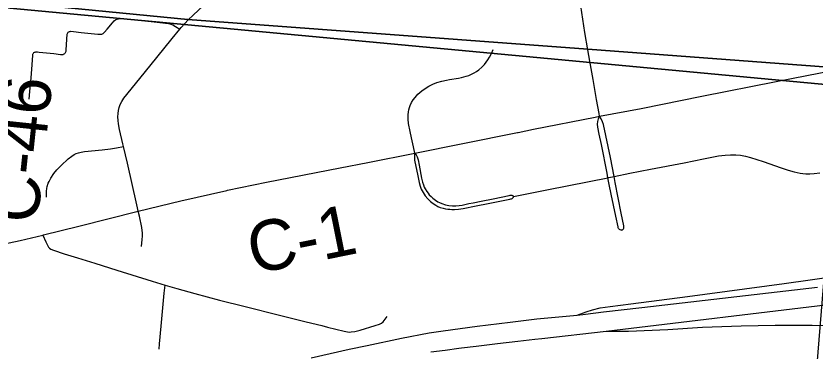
# Model space of a CAD drawing. Extents: x 0 to 34, y 0 to 22.
# Drawn here: x 22.884 to 23.785, y 14.548 to 14.925 of the extents above; entities that cross this region are included whole.
import ezdxf

# ---------------------------------------------------------------- set-up
doc = ezdxf.new("R2010")
doc.units = 0
for name, color, linetype in [('GM_X_City_Street', 7, 'Continuous'), ('GM_X_County_Road', 7, 'Continuous'), ('GM_X_County_Road_Text', 7, 'Continuous'), ('GM_X_Interstate_Route', 7, 'Continuous'), ('GM_X_Section', 7, 'Continuous'), ('GM_X_State_Route', 7, 'Continuous'), ('SH_Border', 7, 'Continuous')]:
    doc.layers.add(name, color=color, linetype=linetype)

msp = doc.modelspace()

# ---------------------------------------------------------------- linework, layer by layer
at = {"layer": 'GM_X_City_Street'}
for points in [[(23.54188, 14.81222), (23.54135, 14.8153), (23.53864, 14.83109), (23.53457, 14.85351), (23.53099, 14.87419), (23.52877, 14.88721), (23.52533, 14.90673), (23.52084, 14.93684), (23.51346, 14.98347), (23.51038, 15.00249), (23.50897, 15.01211), (23.50831, 15.01773), (23.50782, 15.02416), (23.5076, 15.03291), (23.50781, 15.0404), (23.50864, 15.05098), (23.51075, 15.06952), (23.51341, 15.09235), (23.51548, 15.11099)], [(22.94277, 14.90686), (22.94344, 14.90733), (22.94423, 14.90776), (22.94503, 14.90796), (22.946, 14.90799), (22.94886, 14.90772), (22.95749, 14.90677), (22.9761, 14.90474), (22.97875, 14.90463), (22.97967, 14.90467), (22.98075, 14.90496), (22.98211, 14.90571), (22.98372, 14.90698), (22.98666, 14.91035), (22.99264, 14.91759), (22.99465, 14.91978), (22.99649, 14.92115), (22.99801, 14.92186), (22.99963, 14.92225)], [(22.99963, 14.92225), (23.00162, 14.92232), (23.00777, 14.92191), (23.02562, 14.92018), (23.03981, 14.9187), (23.05593, 14.9168), (23.05873, 14.91623), (23.06081, 14.91529), (23.06376, 14.91342), (23.06876, 14.91026)], [(22.90429, 14.88402), (22.90496, 14.88431), (22.90562, 14.88456), (22.90636, 14.88474), (22.90717, 14.88481), (22.90826, 14.88478), (22.91011, 14.88462), (22.92679, 14.88281), (22.93419, 14.88199), (22.93623, 14.88187), (22.937, 14.88196), (22.93772, 14.88218), (22.93844, 14.88254), (22.93905, 14.88302), (22.93958, 14.88362), (22.93998, 14.88428), (22.94024, 14.88495), (22.94047, 14.88579), (22.94065, 14.88696), (22.94176, 14.9046), (22.94197, 14.90557), (22.94229, 14.90626), (22.94277, 14.90686)], [(22.89882, 14.8314), (22.89956, 14.84008), (22.90092, 14.85552), (22.90221, 14.87028), (22.90291, 14.88129), (22.90306, 14.88224), (22.90328, 14.88286), (22.9037, 14.8835), (22.90429, 14.88402)], [(23.33377, 14.77073), (23.33215, 14.77776), (23.32983, 14.78778), (23.32829, 14.79507), (23.32666, 14.80393), (23.32618, 14.8088), (23.32615, 14.81368), (23.3265, 14.81729), (23.32692, 14.81934), (23.32764, 14.82213), (23.32833, 14.82428), (23.32982, 14.82758), (23.33189, 14.83087), (23.33384, 14.83358), (23.33718, 14.83716), (23.3414, 14.84081), (23.34525, 14.84364), (23.34937, 14.84621), (23.3539, 14.84835), (23.35831, 14.85014), (23.36419, 14.85189), (23.36926, 14.85301), (23.37269, 14.85367), (23.38288, 14.85531), (23.38633, 14.85596), (23.38907, 14.85658), (23.39166, 14.85731), (23.39465, 14.85834), (23.39811, 14.85992), (23.40073, 14.86138), (23.40305, 14.86283), (23.40563, 14.86463), (23.409, 14.8675), (23.41209, 14.87069), (23.41419, 14.87333), (23.4161, 14.87599), (23.41798, 14.87893), (23.41998, 14.8829), (23.42194, 14.88756)], [(23.56703, 14.68388), (23.56634, 14.68388), (23.56514, 14.68417), (23.56445, 14.68457), (23.56391, 14.68509), (23.56342, 14.68577), (23.56306, 14.68656), (23.56271, 14.68765), (23.56033, 14.69951), (23.55488, 14.72437), (23.55272, 14.73532), (23.55135, 14.74301), (23.55044, 14.74815), (23.54403, 14.78039), (23.54157, 14.79192), (23.53997, 14.79981), (23.53975, 14.80343), (23.54003, 14.80631), (23.5408, 14.80929), (23.54188, 14.81222)], [(23.56703, 14.68388), (23.56762, 14.68411), (23.56859, 14.68494), (23.56896, 14.68554), (23.56919, 14.68618), (23.56942, 14.68692), (23.56946, 14.6877), (23.56938, 14.68871), (23.56639, 14.70293), (23.55954, 14.73769), (23.55835, 14.74442), (23.55423, 14.76578), (23.54635, 14.80287), (23.54522, 14.80601), (23.54378, 14.80934), (23.54188, 14.81222)], [(22.91835, 14.72097), (22.9185, 14.72794), (22.91871, 14.73067), (22.91916, 14.73323), (22.92036, 14.73666), (22.92133, 14.73887), (22.92335, 14.74265), (22.92669, 14.7477), (22.93, 14.75172), (22.93479, 14.75692), (22.94298, 14.76445), (22.94678, 14.76744), (22.94955, 14.76927), (22.95192, 14.77034), (22.95434, 14.77114), (22.95759, 14.77193), (22.96126, 14.77235), (22.98125, 14.77446), (22.99056, 14.77559), (22.99732, 14.77685), (23.00505, 14.7783)], [(23.33377, 14.77073), (23.3334, 14.76869), (23.33325, 14.76646), (23.33331, 14.76512), (23.33342, 14.76265), (23.33702, 14.74511), (23.33841, 14.73777), (23.33958, 14.73357), (23.34094, 14.7301), (23.34295, 14.72624), (23.34536, 14.72261), (23.34814, 14.71926), (23.35127, 14.71623), (23.35421, 14.71393), (23.35738, 14.71194), (23.35971, 14.71062), (23.3623, 14.70958), (23.36544, 14.70867), (23.3683, 14.70804), (23.37074, 14.70762), (23.37304, 14.70735), (23.37528, 14.7072), (23.37835, 14.7072), (23.38275, 14.70758), (23.3883, 14.70833), (23.40295, 14.71124), (23.41639, 14.71386), (23.4371, 14.71816), (23.44078, 14.71886), (23.44191, 14.71909), (23.44273, 14.71935), (23.44334, 14.71966), (23.44394, 14.72009), (23.44437, 14.7206), (23.44471, 14.72123), (23.44501, 14.72198)], [(23.33377, 14.77073), (23.33532, 14.76869), (23.33638, 14.76635), (23.33741, 14.76321), (23.33855, 14.75707), (23.34134, 14.74256), (23.34232, 14.73802), (23.34336, 14.73489), (23.34434, 14.73244), (23.34546, 14.73028), (23.34706, 14.72756), (23.34853, 14.7256), (23.34993, 14.72379), (23.35202, 14.72163), (23.35397, 14.71989), (23.35693, 14.71763), (23.35948, 14.7159), (23.36164, 14.71486), (23.36407, 14.71386), (23.3682, 14.71249), (23.37184, 14.71168), (23.37616, 14.71116), (23.37993, 14.71116), (23.3837, 14.71158), (23.38705, 14.71221), (23.39452, 14.71377), (23.39938, 14.71481), (23.40851, 14.71669), (23.42194, 14.7193), (23.43993, 14.72305), (23.44102, 14.7232), (23.44202, 14.72326), (23.44296, 14.72317), (23.44377, 14.72295), (23.44448, 14.72255), (23.44501, 14.72198)], [(23.44501, 14.72198), (23.48424, 14.72973), (23.55135, 14.74301), (23.55247, 14.74324), (23.55835, 14.74442), (23.57622, 14.74802), (23.59937, 14.75251), (23.63717, 14.7599), (23.65912, 14.76425), (23.67613, 14.76753), (23.6834, 14.76854), (23.68944, 14.76892), (23.69549, 14.76881), (23.70091, 14.76828), (23.70627, 14.76735), (23.71215, 14.76582), (23.72624, 14.76125), (23.74672, 14.75395), (23.75445, 14.75134), (23.76115, 14.74951), (23.76801, 14.74818), (23.77103, 14.7477), (23.77435, 14.74743), (23.77884, 14.74733), (23.78395, 14.74761), (23.79024, 14.74844)], [(23.02543, 14.66535), (23.0263, 14.67333), (23.02655, 14.67722), (23.02651, 14.6808), (23.02637, 14.6836), (23.02594, 14.68677), (23.02309, 14.69959), (23.0218, 14.70512)], [(22.91411, 14.6783), (22.91765, 14.67062), (22.91938, 14.66688), (22.92067, 14.6648), (22.92175, 14.66351), (22.92326, 14.6625), (22.92613, 14.66135), (22.93848, 14.65737), (22.95333, 14.65279), (22.97287, 14.6466), (22.99774, 14.6387), (23.03753, 14.62645), (23.05208, 14.62199), (23.06538, 14.61793), (23.08574, 14.6124), (23.11343, 14.60506), (23.14233, 14.59774), (23.1809, 14.58795), (23.19479, 14.58453), (23.21108, 14.58049), (23.22879, 14.57624), (23.23537, 14.57457), (23.25412, 14.56989), (23.25772, 14.56917), (23.25988, 14.56903), (23.26183, 14.56909), (23.26598, 14.56963), (23.2719, 14.57114), (23.28907, 14.57629), (23.29367, 14.57795), (23.29625, 14.57916), (23.29797, 14.58067), (23.30034, 14.58348), (23.30229, 14.5865)], [(23.04535, 14.54967), (23.04582, 14.55582), (23.0477, 14.57562), (23.05123, 14.61292), (23.05208, 14.62199)]]:
    msp.add_lwpolyline(points, dxfattribs=at)
at = {"layer": 'GM_X_County_Road'}
for points in [[(23.07814, 14.92095), (23.08359, 14.92619), (23.10087, 14.94225), (23.11282, 14.95365)], [(23.06876, 14.91026), (23.07035, 14.91218), (23.07814, 14.92095)], [(23.00505, 14.7783), (23.0044, 14.78104), (23.00077, 14.79749), (22.99967, 14.80373), (22.99916, 14.80732), (22.99895, 14.81177), (22.99916, 14.81551), (22.99959, 14.81889), (23.00031, 14.82213), (23.00153, 14.82557), (23.00333, 14.82895), (23.0057, 14.83283), (23.02348, 14.85493), (23.04271, 14.87852), (23.05999, 14.89972), (23.06876, 14.91026)], [(23.54188, 14.81222), (23.58881, 14.82108), (23.65722, 14.83479), (23.74118, 14.85128), (23.80831, 14.86452)], [(23.46728, 14.79768), (23.5369, 14.81133), (23.54188, 14.81222)], [(23.33377, 14.77073), (23.3878, 14.78143), (23.44931, 14.79377)], [(23.44931, 14.79377), (23.45028, 14.79397), (23.46728, 14.79768)], [(23.0218, 14.70512), (23.02101, 14.70886), (23.02029, 14.71245), (23.0096, 14.75927), (23.00505, 14.7783)], [(23.24942, 14.75429), (23.28077, 14.76024), (23.33377, 14.77073)], [(23.12165, 14.7286), (23.1226, 14.72881), (23.16639, 14.7378), (23.24942, 14.75429)], [(23.0218, 14.70512), (23.06987, 14.71674), (23.12165, 14.7286)], [(22.91411, 14.6783), (22.91507, 14.67853), (22.95502, 14.68828), (23.0218, 14.70512)], [(22.80712, 14.65654), (22.81739, 14.65808), (22.84318, 14.66273), (22.86908, 14.66796), (22.8887, 14.67237), (22.91411, 14.6783)]]:
    msp.add_lwpolyline(points, dxfattribs=at)
at = {"layer": 'GM_X_Interstate_Route'}
msp.add_line((23.54919, 14.56996), (23.87347, 14.60919), dxfattribs=at)
for points in [[(23.21665, 14.54004), (23.25973, 14.54955), (23.27975, 14.55401), (23.31866, 14.56222), (23.34982, 14.568), (23.36578, 14.57046), (23.40396, 14.5756), (23.44098, 14.58003), (23.47118, 14.58384), (23.51682, 14.5881), (23.52607, 14.58925), (23.54643, 14.59167), (23.58963, 14.59675), (23.78774, 14.6197)], [(23.4689, 14.56086), (23.47695, 14.56181), (23.54919, 14.56996)], [(23.38612, 14.55105), (23.40291, 14.55302), (23.42696, 14.55596), (23.44979, 14.55862), (23.4689, 14.56086)], [(23.3517, 14.54668), (23.36773, 14.54877), (23.38316, 14.55071), (23.38612, 14.55105)]]:
    msp.add_lwpolyline(points, dxfattribs=at)
at = {"layer": 'GM_X_Section'}
for points in [[(22.93242, 15.94904), (23.88549, 15.85603), (23.90516, 15.85455), (23.81234, 14.84657), (22.83652, 14.9377)], [(23.81234, 14.84657), (23.73099, 13.84446), (22.74129, 13.94338), (22.83652, 14.9377)]]:
    msp.add_lwpolyline(points, close=True, dxfattribs=at)
at = {"layer": 'GM_X_State_Route'}
for points in [[(23.51682, 14.5881), (23.52664, 14.59182), (23.53408, 14.59408), (23.54249, 14.59618), (23.55394, 14.59785), (23.57707, 14.60084), (23.64117, 14.60912), (23.75019, 14.62379), (23.81114, 14.63228)], [(23.54919, 14.56996), (23.57467, 14.57015), (23.61881, 14.5719), (23.65795, 14.57434), (23.70143, 14.57611), (23.73997, 14.5769), (23.78161, 14.57696), (23.82699, 14.57634), (23.87668, 14.57463), (23.93628, 14.57193), (24.00132, 14.56928), (24.01909, 14.5695)]]:
    msp.add_lwpolyline(points, dxfattribs=at)
at = {"layer": 'SH_Border'}
for points in [[(22.51637, 19.03183), (22.51637, 14.97433), (22.53748, 14.97157), (22.5519, 14.96981), (22.58542, 14.9669), (22.62619, 14.96271), (22.67598, 14.95801), (22.69418, 14.9563), (22.71892, 14.95402), (22.74245, 14.95174), (22.74837, 14.95098), (22.75142, 14.95053), (22.75414, 14.94979), (22.75606, 14.949), (22.75808, 14.9478), (22.82376, 14.94586), (22.83456, 14.94555), (23.07791, 14.92148), (23.52854, 14.88774), (23.81459, 14.86633)], [(23.81459, 14.86633), (23.52854, 14.88774), (23.07791, 14.92148), (22.83456, 14.94555), (22.82376, 14.94586), (22.75808, 14.9478), (22.75606, 14.949), (22.75414, 14.94979), (22.75142, 14.95053), (22.74837, 14.95098), (22.74245, 14.95174), (22.71892, 14.95402), (22.69418, 14.9563), (22.67598, 14.95801), (22.62619, 14.96271), (22.58542, 14.9669), (22.5519, 14.96981), (22.53748, 14.97157), (22.51637, 14.97433), (22.51637, 13.46181)]]:
    msp.add_lwpolyline(points, dxfattribs=at)

# ---------------------------------------------------------------- texts
at = {"layer": 'GM_X_County_Road_Text'}
for s, rotation, p in [('C-46', 83.99442, (22.90803, 14.69001)), ('C-1', 11.39688, (23.15133, 14.6341))]:
    msp.add_text(s, height=0.056818, rotation=rotation, dxfattribs=at).set_placement(p)

doc.saveas('drawing.dxf')
